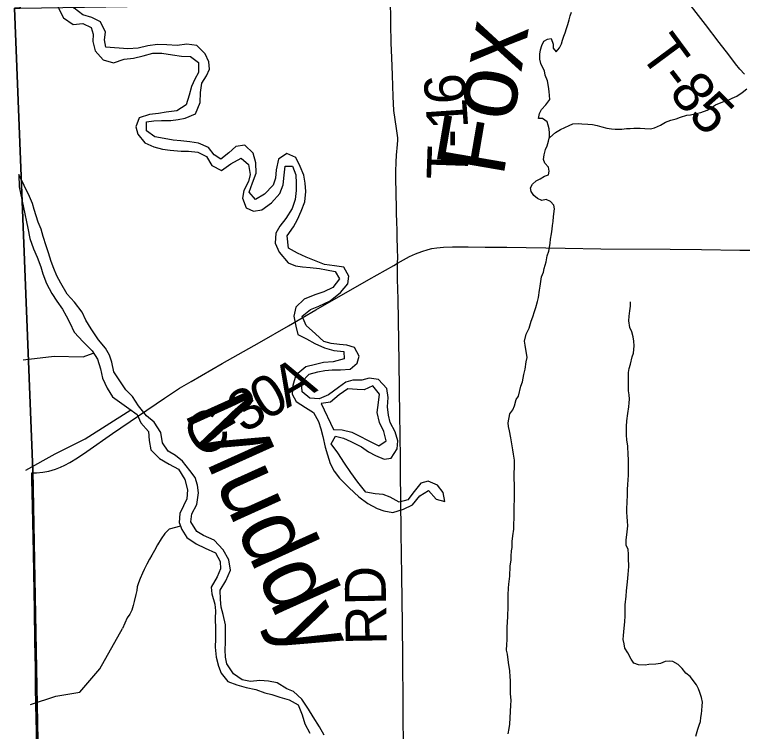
# Model space of a CAD drawing. Extents: x 1985906 to 2360102, y 891258 to 1222054.
# Drawn here: x 2071562 to 2076886, y 1019793 to 1025035 of the extents above; entities that cross this region are included whole.
import ezdxf

# ---------------------------------------------------------------- set-up
doc = ezdxf.new("R2010")
doc.units = 0
for name, color, linetype in [('GM_X_Adjacent_County', 7, 'Continuous'), ('GM_X_County', 7, 'Continuous'), ('GM_X_County_Road', 7, 'Continuous'), ('GM_X_County_Road_Text', 7, 'Continuous'), ('GM_X_Major_River', 7, 'Continuous'), ('GM_X_Major_River_Text', 7, 'Continuous'), ('GM_X_Minor_River', 7, 'Continuous'), ('GM_X_Minor_River_Text', 7, 'Continuous'), ('GM_X_Township', 7, 'Continuous'), ('GM_X_Township_Road', 7, 'Continuous'), ('GM_X_Township_Road_Text', 7, 'Continuous')]:
    doc.layers.add(name, color=color, linetype=linetype)

msp = doc.modelspace()

# ---------------------------------------------------------------- linework, layer by layer
at = {"layer": 'GM_X_Adjacent_County'}
msp.add_lwpolyline([(2071926.7, 1054555.3), (2072166.7, 1051922.6), (2072218.3, 1051577.8), (2072142.8, 1047459), (2072178.7, 1046252), (2072112.2, 1041354.4), (2072120.2, 1038512.6), (2072055.1, 1036106.6), (2072018.3, 1033424.1), (2071939.9, 1030867.8), (2071602.1, 1025081.7), (2071562, 1025081.6), (2071696.9, 1021700.4), (2071829.8, 1014456.9), (2071852.3, 1012905.1), (2071861.2, 1011952), (2071887.5, 1008769)], dxfattribs=at)
at = {"layer": 'GM_X_County'}
msp.add_lwpolyline([(2071887.5, 1008769), (2071861.2, 1011952), (2071852.3, 1012905.1), (2071829.8, 1014456.9), (2071696.9, 1021700.4), (2071562, 1025081.6), (2071602.1, 1025081.7), (2071939.9, 1030867.8), (2072018.3, 1033424.1), (2072055.1, 1036106.6), (2072120.2, 1038512.6), (2072112.2, 1041354.4), (2072178.7, 1046252), (2072142.8, 1047459), (2072218.3, 1051577.8), (2072166.7, 1051922.6), (2071926.7, 1054555.3)], dxfattribs=at)
at = {"layer": 'GM_X_County_Road'}
for points in [[(2074363.8, 1023217), (2074450, 1023264.6), (2074494.1, 1023285.7), (2074539.6, 1023303.3), (2074586.4, 1023317.6), (2074614.9, 1023323.7), (2074650.1, 1023330), (2074698.9, 1023334.4), (2074764.3, 1023336.9), (2074879.1, 1023336.2), (2075003.2, 1023334.4), (2075161.3, 1023332.9), (2075590.2, 1023327.4), (2075850.3, 1023322.8), (2076356.6, 1023318.9), (2076586.2, 1023315.8), (2076867.7, 1023312.7), (2076963, 1023312.3), (2077040.4, 1023312.3)], [(2071687.6, 1021683), (2071723.6, 1021683.7), (2071768.9, 1021688.3), (2071811.9, 1021696), (2071861.7, 1021709.8), (2071898.5, 1021724.4), (2071930, 1021738.9), (2071966.5, 1021758.5), (2072022.6, 1021793.2), (2072090.4, 1021839.7), (2072279.2, 1021970.8), (2072658.4, 1022230.8), (2072768.7, 1022301.9), (2072853, 1022352.6), (2073081.3, 1022482.7), (2073352.3, 1022637.2), (2073566.3, 1022759.3), (2073765.1, 1022874.7), (2074152.2, 1023097.5), (2074335.5, 1023200.7), (2074363.8, 1023217)], [(2071724.7, 1019633.2), (2071721.9, 1019797.2), (2071720.5, 1019879.2), (2071715.4, 1020108.5), (2071714.1, 1020256.1), (2071710.5, 1020452.7), (2071708, 1020682.3), (2071704.8, 1020813.6), (2071700.5, 1021099.1), (2071693.8, 1021436.8), (2071688.6, 1021633.8), (2071687.6, 1021683)]]:
    msp.add_lwpolyline(points, dxfattribs=at)
at = {"layer": 'GM_X_Major_River'}
for points in [[(2071594.5, 1023864.4), (2071596.5, 1023775.9)], [(2072375, 1022290.3), (2072287.9, 1022422.8), (2072273.6, 1022493), (2072255.4, 1022543), (2072227.2, 1022595.1), (2072175, 1022657.1), (2072122.7, 1022737.1), (2072084.5, 1022801.1), (2072056.2, 1022859.2), (2072000, 1022931.2), (2071945.7, 1022991.1), (2071901.4, 1023071.2), (2071871.2, 1023123.2), (2071849, 1023177.2), (2071830.8, 1023229.3), (2071810.6, 1023293.4), (2071794.4, 1023343.5), (2071772.1, 1023411.6), (2071755.9, 1023465.7), (2071733.7, 1023517.7), (2071705.4, 1023610.4), (2071694.1, 1023652.8), (2071671, 1023704), (2071594.5, 1023864.4)], [(2071596.5, 1023775.9), (2071660.2, 1023472.1), (2071674.2, 1023397.2), (2071700.5, 1023321.1), (2071726.7, 1023261), (2071753, 1023188.9), (2071769.2, 1023138.8), (2071795.4, 1023068.8), (2071833.7, 1022994.7), (2071871.9, 1022938.7), (2071912.1, 1022880.7), (2071940.3, 1022830.7), (2071966.5, 1022780.6), (2071996.8, 1022712.6), (2072063.1, 1022642.6), (2072129.3, 1022574.7), (2072169.5, 1022514.7), (2072191.8, 1022444.6), (2072204.1, 1022376.4), (2072238.3, 1022302.4), (2072278.6, 1022240.3), (2072397.8, 1022154.3)], [(2073826.8, 1019765.7), (2073792.4, 1019825.6), (2073746, 1019899.4), (2073711.7, 1019955.3), (2073663.3, 1020029.1), (2073603, 1020084.8), (2073552.9, 1020104.5), (2073482.7, 1020148.2), (2073418.6, 1020159.8), (2073356.6, 1020165.4), (2073288.7, 1020157), (2073226.6, 1020170.7), (2073164.3, 1020214.4), (2073114, 1020286.2), (2073105.7, 1020336.2), (2073101.4, 1020390.2), (2073105.1, 1020442.3), (2073104.7, 1020510.4), (2073104.4, 1020572.5), (2073088, 1020646.5), (2073073.7, 1020700.4), (2073067.4, 1020756.5), (2073067, 1020826.6), (2073106.6, 1020894.9), (2073140.2, 1020971.2), (2073129.8, 1021047.2), (2073087.4, 1021121), (2073021, 1021190.8), (2072944.8, 1021226.3), (2072894.7, 1021254.1), (2072852.3, 1021325.9), (2072857.9, 1021384), (2072895.6, 1021452.3), (2072907.1, 1021538.5), (2072900.8, 1021594.5), (2072882.5, 1021648.5), (2072844.2, 1021700.3), (2072789.9, 1021768.1), (2072739.6, 1021809.8), (2072685.5, 1021841.6), (2072645.1, 1021903.4), (2072632.7, 1021979.4), (2072582.3, 1022053.2), (2072528, 1022101), (2072469.7, 1022174.7), (2072425.3, 1022242.5), (2072375, 1022290.3)], [(2072397.8, 1022154.3), (2072460, 1022110.6), (2072486.3, 1022048.7), (2072542.7, 1021984.9), (2072547, 1021918.9), (2072559.4, 1021850.8), (2072621.8, 1021789.1), (2072692, 1021747.5), (2072760.2, 1021709.8), (2072806.6, 1021636), (2072827, 1021560.1), (2072821.3, 1021493.9), (2072797.6, 1021441.7), (2072772, 1021385.5), (2072766.3, 1021321.4), (2072784.6, 1021269.5), (2072820.9, 1021209.6), (2072891.2, 1021163.9), (2072955.3, 1021132.3), (2073031.5, 1021098.7), (2073065.8, 1021034.8), (2073068.1, 1020982.8), (2073044.5, 1020922.6), (2072998.9, 1020848.2), (2073005.2, 1020798.2), (2073027.6, 1020724.2), (2073031.8, 1020674.2), (2073028.1, 1020618.1), (2073030.6, 1020542), (2073031, 1020469.9), (2073029.3, 1020409.8), (2073037.7, 1020335.8), (2073054.1, 1020269.8), (2073072.3, 1020217.8), (2073120.7, 1020158), (2073188.8, 1020132.4), (2073256.9, 1020114.8), (2073327, 1020099.2), (2073393.1, 1020075.5), (2073443.2, 1020061.8), (2073501.3, 1020044.1), (2073569.4, 1020022.5), (2073635.5, 1019986.8), (2073665.9, 1019914.9), (2073684.3, 1019849), (2073720.7, 1019781.1)]]:
    msp.add_lwpolyline(points, dxfattribs=at)
at = {"layer": 'GM_X_Minor_River'}
for points in [[(2072310.6, 1025418.7), (2072244.6, 1025436.5), (2072194.5, 1025454.3), (2072132.4, 1025492.2), (2072080.3, 1025514.1), (2072008.2, 1025527.9), (2071932.3, 1025509.5), (2071876.5, 1025447.2), (2071848.7, 1025380.9), (2071835, 1025308.7), (2071835.3, 1025244.5), (2071839.4, 1025194.4), (2071865.7, 1025124.3), (2071894, 1025062.3), (2071920.1, 1025010.2), (2071990.3, 1024962.3), (2072062.3, 1024968.6), (2072122.4, 1024940.8), (2072136.6, 1024890.7), (2072134.8, 1024838.5), (2072151.1, 1024770.4), (2072211.3, 1024704.5), (2072285.4, 1024682.7), (2072363.8, 1024709.1)], [(2072391.4, 1024783.3), (2072229, 1024796.8), (2072218.8, 1024848.9), (2072226.6, 1024905), (2072190.3, 1024981.1), (2072128.2, 1025013), (2072062.1, 1025032.8), (2071997.9, 1025080.7), (2071955.6, 1025146.7), (2071947.4, 1025198.8), (2071941.2, 1025254.9), (2071935, 1025325.1), (2071954.8, 1025379.3), (2071986.5, 1025443.6), (2072054.6, 1025435.8), (2072114.7, 1025409.9), (2072164.8, 1025384), (2072236.9, 1025342.2), (2072302.9, 1025338.4)], [(2075183.8, 1022114.2), (2075205.7, 1022144.4), (2075217.5, 1022172.5), (2075231.3, 1022218.8), (2075247.2, 1022244.9), (2075264.9, 1022317.3), (2075276.7, 1022349.4), (2075286.5, 1022403.7), (2075296.3, 1022441.9), (2075304, 1022496.1), (2075311.9, 1022526.2), (2075297.4, 1022616.5), (2075291.2, 1022646.6), (2075303, 1022696.8), (2075326.8, 1022741.1), (2075340.6, 1022793.3), (2075352.4, 1022823.5), (2075364.2, 1022863.7), (2075374.1, 1022891.9), (2075385.9, 1022936.1), (2075393.8, 1022966.2), (2075401.5, 1023020.4), (2075405.3, 1023048.6), (2075417, 1023116.9), (2075430.9, 1023151), (2075436.7, 1023177.2), (2075450.5, 1023225.4), (2075458.3, 1023269.6), (2075470.1, 1023305.8), (2075474, 1023331.9), (2075479.9, 1023362), (2075481.7, 1023392.2), (2075489.5, 1023430.3), (2075493.4, 1023464.5), (2075497.2, 1023492.6), (2075501.1, 1023522.7), (2075502.9, 1023558.8), (2075510.6, 1023615.1), (2075506.5, 1023641.2), (2075482.3, 1023667.1), (2075450.1, 1023683), (2075418.1, 1023674.9), (2075386, 1023690.8), (2075359.8, 1023712.7), (2075339.6, 1023740.7), (2075335.5, 1023768.8), (2075351.4, 1023795), (2075377.3, 1023819.2), (2075405.3, 1023833.4), (2075437.2, 1023853.6), (2075467.2, 1023861.8), (2075471.1, 1023889.9), (2075467, 1023918), (2075440.7, 1023948), (2075430.6, 1023976), (2075434.4, 1024010.2), (2075446.2, 1024048.3), (2075458.1, 1024074.5), (2075468, 1024108.7), (2075473.8, 1024140.8), (2075475.7, 1024166.9), (2075471.5, 1024199), (2075465.3, 1024225.1), (2075457.2, 1024251.1), (2075423, 1024275), (2075395, 1024274.9), (2075400.8, 1024311.1), (2075416.7, 1024341.2), (2075448.5, 1024373.5), (2075476.4, 1024413.8), (2075474.2, 1024441.9), (2075472.1, 1024472), (2075467.9, 1024508.1), (2075459.7, 1024550.2), (2075443.4, 1024592.3), (2075437.2, 1024624.4), (2075423.1, 1024650.4), (2075410.9, 1024676.4), (2075402.7, 1024708.5), (2075404.5, 1024744.7), (2075408.4, 1024776.8), (2075418.2, 1024808.9), (2075434.1, 1024839.1), (2075460.1, 1024855.3), (2075486.1, 1024859.4), (2075500.3, 1024819.4), (2075502.5, 1024789.3), (2075522.7, 1024763.3), (2075546.6, 1024791.5), (2075562.4, 1024821.7), (2075570.3, 1024847.8), (2075578.2, 1024875.9), (2075590.1, 1024902.1), (2075597.9, 1024932.2), (2075607.8, 1024962.4), (2075617.6, 1024996.5), (2075625.5, 1025026.7), (2075635.4, 1025052.8)], [(2073330.3, 1023875.8), (2073325.9, 1023949.8), (2073307.5, 1024021.8), (2073247.1, 1024079.5), (2073181.2, 1024069.1), (2073129.5, 1024022.8), (2073071.7, 1023978.4), (2073021.6, 1024010.1), (2072981.3, 1024061.9), (2072907.1, 1024093.6), (2072845.1, 1024103.2), (2072779, 1024110.8), (2072723, 1024116.5), (2072656.9, 1024128.1), (2072588.9, 1024139.7), (2072526.7, 1024183.4), (2072526.3, 1024251.5), (2072580.2, 1024257.8), (2072636.2, 1024260.2), (2072706.2, 1024260.6), (2072758.2, 1024266.9), (2072810.1, 1024277.2), (2072885.9, 1024309.7), (2072919.5, 1024392), (2072921.1, 1024466.1), (2072930.7, 1024534.2), (2072966.4, 1024586.5), (2072988.1, 1024636.7), (2072983.8, 1024688.7), (2072955.5, 1024746.6), (2072895.2, 1024808.3), (2072823.2, 1024817.9), (2072751.2, 1024807.5), (2072675.2, 1024813), (2072607.2, 1024816.6), (2072537.2, 1024806.2), (2072467.3, 1024789.8), (2072391.4, 1024783.3)], [(2072363.8, 1024709.1), (2072431.8, 1024715.5), (2072503.6, 1024733.9), (2072573.5, 1024752.4), (2072639.5, 1024752.8), (2072717.6, 1024739.2), (2072783.6, 1024731.6), (2072849.6, 1024728), (2072907.9, 1024684.2), (2072908.3, 1024612.2), (2072880.5, 1024561.9), (2072856.8, 1024509.7), (2072839.2, 1024445.6), (2072817.6, 1024375.4), (2072747.8, 1024330.9), (2072671.9, 1024320.4), (2072615.9, 1024312.1), (2072550, 1024303.7), (2072474.1, 1024279.2), (2072448.5, 1024213), (2072464.8, 1024159), (2072515.1, 1024097.2), (2072581.3, 1024067.6), (2072643.4, 1024050), (2072699.4, 1024042.3), (2072779.4, 1024036.7), (2072833.4, 1024035.1), (2072901.5, 1024027.4), (2072965.6, 1023997.8), (2073004, 1023931.9), (2073076.2, 1023894.3), (2073143.9, 1023942.8), (2073219.7, 1023985.3), (2073273.9, 1023937.5), (2073284.3, 1023865.5), (2073272.6, 1023813.4), (2073239, 1023747.1), (2073229.3, 1023691), (2073255.7, 1023621), (2073309.8, 1023597.3), (2073369.7, 1023605.7), (2073441.4, 1023658.2), (2073503.1, 1023726.6), (2073526.7, 1023790.8), (2073534.3, 1023861), (2073542, 1023925.1), (2073593.9, 1023927.4), (2073618.3, 1023863.5), (2073622.6, 1023801.4), (2073622.9, 1023747.3), (2073613.3, 1023683.2), (2073591.6, 1023617), (2073546, 1023544.7), (2073502.4, 1023488.3), (2073472.6, 1023436.1), (2073467, 1023364), (2073497.4, 1023298.1), (2073563.8, 1023220.4), (2073615.9, 1023196.7), (2073668, 1023191), (2073724, 1023185.3), (2073792, 1023177.7), (2073844.1, 1023168), (2073908.1, 1023156.3), (2073938.4, 1023102.4), (2073888.8, 1023038.1), (2073825, 1023007.7), (2073757.1, 1022985.2), (2073681.3, 1022952.8), (2073619.6, 1022894.3), (2073604, 1022828.2), (2073618.3, 1022756.2), (2073632.7, 1022694.2), (2073696.8, 1022664.5), (2073759, 1022628.8), (2073829.2, 1022597.2), (2073897.3, 1022577.6), (2073969.3, 1022570), (2073971.6, 1022517.9), (2073891.7, 1022495.4), (2073821.8, 1022491), (2073763.9, 1022476.7), (2073692, 1022458.2), (2073620.3, 1022397.7), (2073596.7, 1022323.5), (2073593.1, 1022259.4), (2073621.4, 1022205.5), (2073689.6, 1022161.9), (2073747.8, 1022124.2), (2073786.2, 1022058.3), (2073802.4, 1022004.3), (2073816.8, 1021948.3), (2073833.2, 1021870.3), (2073851.5, 1021814.4), (2073869.8, 1021752.4), (2073900.1, 1021696.5), (2073938.4, 1021644.7), (2074008.8, 1021573), (2074081.1, 1021507.4), (2074145.4, 1021459.7), (2074213.6, 1021424)], [(2075473.2, 1024137.6), (2075477.8, 1024136.8), (2075517.7, 1024173.1), (2075555.7, 1024193.4), (2075585.7, 1024209.6), (2075617.6, 1024223.8), (2075645.6, 1024235.9), (2075685.7, 1024238.1), (2075711.8, 1024236.2), (2075753.9, 1024232.4), (2075787.9, 1024230.6), (2075824, 1024224.7), (2075856.2, 1024214.8), (2075894.3, 1024202.9), (2075928.4, 1024199.1), (2075954.4, 1024197.2), (2076004.5, 1024197.4), (2076036.6, 1024201.6), (2076064.6, 1024201.7), (2076090.7, 1024203.8), (2076138.7, 1024204.1), (2076172.8, 1024202.2), (2076212.9, 1024200.4), (2076242.9, 1024206.6), (2076286.9, 1024224.8), (2076322.9, 1024247.1), (2076360.9, 1024263.3), (2076400.9, 1024271.5), (2076432.9, 1024285.7), (2076478.9, 1024298), (2076507, 1024302.1), (2076535, 1024308.3), (2076581, 1024318.5), (2076627, 1024336.8), (2076653, 1024351), (2076688.9, 1024375.2), (2076742.9, 1024397.5), (2076780.9, 1024409.8), (2076810.9, 1024423.9), (2076844.9, 1024438.2), (2076882.8, 1024464.4), (2076916.8, 1024492.7)], [(2074213.6, 1021424), (2074263.7, 1021406.3), (2074327.7, 1021392.7), (2074407.6, 1021417.2), (2074473.4, 1021449.6), (2074527.1, 1021516), (2074588.8, 1021554.4), (2074645.2, 1021490.7), (2074709.3, 1021475), (2074696.9, 1021541), (2074656.6, 1021592.8), (2074586.5, 1021622.5), (2074532.6, 1021608.1), (2074484.9, 1021547.8), (2074437.2, 1021485.4), (2074375.3, 1021469), (2074309.1, 1021504.7), (2074259, 1021526.4), (2074199, 1021530.1), (2074131, 1021541.7), (2074072.6, 1021615.4), (2074022.2, 1021687.2), (2073975.8, 1021755), (2073925.4, 1021830.8), (2073877, 1021896.6), (2073908.7, 1021950.9), (2073966.8, 1021937.2), (2074020.9, 1021913.5), (2074099.1, 1021873.9), (2074151.3, 1021838.2), (2074201.5, 1021810.4), (2074265.6, 1021782.8), (2074317.6, 1021791.1), (2074361.2, 1021859.4), (2074364.9, 1021917.5), (2074346.5, 1021983.5), (2074310.1, 1022051.4), (2074295.8, 1022105.3), (2074289.5, 1022167.4), (2074295.1, 1022235.5), (2074284.8, 1022301.5), (2074224.4, 1022367.2), (2074154.4, 1022376.8), (2074102.5, 1022360.5), (2074036.5, 1022362.1), (2073984.6, 1022345.8), (2073930.8, 1022307.4), (2073859.1, 1022253), (2073789.2, 1022224.5), (2073721.2, 1022230.1), (2073665, 1022275.8), (2073660.6, 1022345.9), (2073716.3, 1022404.3), (2073780.2, 1022422.7), (2073832.1, 1022431), (2073884.1, 1022437.3), (2073946.1, 1022435.7), (2074016, 1022442.1), (2074067.8, 1022484.5), (2074083.5, 1022536.6), (2074047.2, 1022600.5), (2073993.1, 1022616.2), (2073939.1, 1022621.9), (2073877, 1022629.5), (2073824.9, 1022645.2), (2073762.6, 1022700.9), (2073694.3, 1022760.6), (2073665.9, 1022828.5), (2073725.7, 1022878.9), (2073787.5, 1022901.3), (2073871.3, 1022941.9), (2073945, 1023002.4), (2073998.6, 1023066.8), (2074006.3, 1023122.9), (2073970, 1023186.7), (2073901.9, 1023196.3), (2073829.9, 1023207.9), (2073755.7, 1023235.5), (2073695.6, 1023261.2), (2073631.4, 1023290.9), (2073565.2, 1023326.5), (2073556.7, 1023416.6), (2073602.4, 1023482.9), (2073632.1, 1023537.2), (2073657.7, 1023597.4), (2073685.4, 1023665.6), (2073693, 1023741.8), (2073688.6, 1023801.8), (2073678.3, 1023859.8), (2073652, 1023923.7), (2073619.6, 1023989.6), (2073553.4, 1024019.3), (2073491.7, 1023976.9), (2073476.1, 1023898.7), (2073470.4, 1023838.6), (2073452.7, 1023786.4), (2073391.1, 1023722), (2073325.3, 1023683.5), (2073277, 1023735.3), (2073302.7, 1023803.5), (2073330.3, 1023875.8)], [(2076593.5, 1020006.9), (2076587.3, 1020041), (2076575.1, 1020077.1), (2076564.9, 1020105.2), (2076548.7, 1020133.2), (2076502.3, 1020195.2), (2076472.1, 1020219.2), (2076445.9, 1020253.2), (2076415.7, 1020283.1), (2076377.5, 1020305), (2076349.4, 1020306.9), (2076319.4, 1020302.8), (2076285.4, 1020288.5), (2076251.4, 1020284.4), (2076201.3, 1020282.2), (2076173.3, 1020278), (2076125.2, 1020279.8), (2076091, 1020291.7), (2076070.8, 1020321.7), (2076048.6, 1020367.8), (2076026.3, 1020401.8), (2076020.2, 1020433.9), (2076014, 1020464), (2076015.8, 1020494.1), (2076017.7, 1020520.2), (2076025.3, 1020596.5), (2076027.1, 1020634.6), (2076026.8, 1020686.8), (2076028.7, 1020719), (2076034.4, 1020781.2), (2076038.2, 1020821.4), (2076045.8, 1020885.6), (2076049.6, 1020939.9), (2076055.3, 1020998.1), (2076052.9, 1021060.3), (2076052.8, 1021086.4), (2076050.6, 1021124.5), (2076036.4, 1021152.6), (2076036.2, 1021190.7), (2076041.9, 1021251), (2076047.7, 1021295.2), (2076045.5, 1021331.3), (2076043.4, 1021361.4), (2076041.2, 1021395.5), (2076041, 1021423.6), (2076042.8, 1021465.8), (2076044.5, 1021526), (2076044.3, 1021562.1), (2076048.1, 1021598.2), (2076051.8, 1021666.5), (2076051.2, 1021782.9), (2076049, 1021815), (2076046.7, 1021879.3), (2076040.4, 1021925.4), (2076038.2, 1021959.5), (2076038, 1021995.7), (2076037.9, 1022021.7), (2076039.7, 1022063.9), (2076047.4, 1022118.1), (2076055.2, 1022166.3), (2076057, 1022196.5), (2076058.9, 1022222.6), (2076056.7, 1022254.7), (2076052.6, 1022282.8), (2076051.9, 1022417.2), (2076057.7, 1022447.4), (2076067.6, 1022479.5), (2076079.3, 1022531.8), (2076089.2, 1022557.9), (2076092.9, 1022612.1), (2076090.8, 1022646.2), (2076086.6, 1022678.3), (2076076.4, 1022714.4), (2076062.2, 1022746.5), (2076055.9, 1022794.6), (2076057.7, 1022828.8), (2076061.5, 1022868.9), (2076067.4, 1022903.1), (2076067.2, 1022935.2)], [(2071625.9, 1022511), (2071852.4, 1022537.7), (2072063.3, 1022532.6), (2072137.1, 1022558.3)], [(2073894.5, 1022000.9), (2073958.5, 1021997.2), (2074028.6, 1021981.6), (2074078.7, 1021955.9), (2074152.9, 1021918.3), (2074227.1, 1021880.7), (2074278.9, 1021917), (2074262.5, 1021987), (2074232.1, 1022050.9), (2074213.7, 1022124.9), (2074223.3, 1022197), (2074231, 1022259.2), (2074182.7, 1022318.9), (2074118.8, 1022290.5), (2074068.8, 1022294.2), (2073998.8, 1022297.8), (2073935.1, 1022253.4), (2073873.4, 1022201), (2073805.4, 1022190.6)], [(2073805.4, 1022190.6), (2073894.5, 1022000.9)], [(2071644.7, 1021702.1), (2071858.7, 1021821.8), (2072078.3, 1021932.9), (2072413.4, 1022143.3)], [(2075172, 1019775.6), (2075179.8, 1019813.8), (2075183.6, 1019845.9), (2075189.2, 1019938.2), (2075192.9, 1019984.4), (2075194.7, 1020018.6), (2075190.5, 1020070.7), (2075190, 1020165.1), (2075187.8, 1020191.2), (2075185.6, 1020235.3), (2075175.3, 1020295.5), (2075166.9, 1020357.7), (2075160.8, 1020385.8), (2075162.5, 1020427.9), (2075164.4, 1020462.1), (2075163.9, 1020554.4), (2075167.7, 1020592.5), (2075169.5, 1020632.7), (2075173.1, 1020705), (2075172.7, 1020791.3), (2075174.4, 1020839.5), (2075178.3, 1020869.6), (2075184, 1020927.9), (2075187.6, 1021000.1), (2075193.4, 1021046.3), (2075195.2, 1021074.4), (2075197, 1021112.6), (2075200.9, 1021138.7), (2075202.7, 1021180.9), (2075206.5, 1021223), (2075214.2, 1021271.2), (2075214, 1021315.4), (2075215.9, 1021345.5), (2075215.3, 1021449.9), (2075219.2, 1021480), (2075218.5, 1021604.5), (2075216.4, 1021632.6), (2075216.2, 1021660.7), (2075217.8, 1021743), (2075217.6, 1021775.1), (2075211.4, 1021819.2), (2075207.2, 1021851.3), (2075196.9, 1021909.5), (2075190.7, 1021939.6), (2075182.4, 1021989.7), (2075174.2, 1022021.8), (2075172.1, 1022049.9), (2075183.8, 1022114.2)], [(2072776.1, 1021293.6), (2072693.4, 1021271.7), (2072661.5, 1021239.4), (2072633.7, 1021201.2), (2072607.8, 1021156.9), (2072586, 1021114.6), (2072566.1, 1021082.4), (2072548.3, 1021052.2), (2072530.4, 1021016), (2072510.6, 1020977.8), (2072496.7, 1020949.6), (2072480.9, 1020911.4), (2072469, 1020879.2), (2072459.2, 1020849.1), (2072457.3, 1020823), (2072449.4, 1020792.8), (2072437.7, 1020742.6), (2072429.8, 1020714.4), (2072420, 1020678.3), (2072406.1, 1020650.1), (2072386.2, 1020623.9), (2072352.2, 1020545.8)], [(2071677.6, 1019990.2), (2071863.8, 1020049.5), (2072038.5, 1020080.1), (2072186.1, 1020249.8), (2072352.2, 1020545.8)], [(2076544.7, 1019757.8), (2076560.5, 1019810), (2076568.3, 1019838.2), (2076578.2, 1019866.3), (2076582.1, 1019894.5), (2076585.9, 1019920.6), (2076589.8, 1019946.7), (2076591.6, 1019978.8), (2076593.5, 1020006.9)]]:
    msp.add_lwpolyline(points, dxfattribs=at)
at = {"layer": 'GM_X_Township'}
msp.add_lwpolyline([(2071887.5, 1008769), (2071861.2, 1011952), (2071852.3, 1012905.1), (2071829.8, 1014456.9), (2071696.9, 1021700.4), (2071562, 1025081.6), (2071602.1, 1025081.7), (2074264, 1025122.4), (2076405.9, 1025155.2), (2079654.5, 1025204.9), (2081728.4, 1025236.6), (2086577.8, 1025306.1), (2087095.5, 1025303.4), (2089225.7, 1025330.9), (2092097.4, 1025367.8), (2095094.6, 1025388.3)], dxfattribs=at)
at = {"layer": 'GM_X_Township_Road'}
for points in [[(2076900.1, 1024599.4), (2076866.7, 1024635.9), (2076835.1, 1024673.8), (2076785.3, 1024739.3), (2076716.6, 1024831.3), (2076616.3, 1024961), (2076436.7, 1025194.6)], [(2074363.8, 1023217), (2074364.9, 1023257.6), (2074364.9, 1023278), (2074363.8, 1023297.8), (2074362, 1023330.8), (2074361.7, 1023347.7), (2074361.3, 1023380.5), (2074360.1, 1023422.3), (2074359.2, 1023466.2), (2074358.3, 1023508.4), (2074356.5, 1023591), (2074352.6, 1023757.2), (2074351.2, 1023810), (2074351.6, 1023839.4), (2074350.3, 1023888.3), (2074352.1, 1023955.3), (2074356.6, 1024005.6), (2074362.6, 1024083.9), (2074364.7, 1024116.9), (2074365, 1024133.8), (2074363.8, 1024150.4), (2074355.7, 1024202.1), (2074345, 1024267.6), (2074336, 1024333.2), (2074330.6, 1024436.4), (2074325.3, 1024590.7), (2074320.7, 1024721.7), (2074317.2, 1024826.8), (2074313.7, 1024967.6), (2074310.7, 1025168.4)], [(2074406.2, 1019610), (2074404.4, 1019985.1), (2074401.8, 1020329.7), (2074399.2, 1020577.4), (2074394.4, 1020934.1), (2074389.8, 1021245.9), (2074387.3, 1021492.1), (2074385.9, 1021673.2), (2074384.1, 1021779.1), (2074381.2, 1021968.2), (2074379.1, 1022099.5), (2074374.5, 1022493.5), (2074366.9, 1022953.1), (2074363.3, 1023100.7), (2074362.1, 1023182.8), (2074363.8, 1023217)]]:
    msp.add_lwpolyline(points, dxfattribs=at)

# ---------------------------------------------------------------- texts
at = {"layer": 'GM_X_County_Road_Text'}
for s, rotation, p in [('A', 29.9563, (2073555.4, 1022153.8)), ('0', 29.9869, (2073395.4, 1022061.4)), ('3', 30.0873, (2073235.6, 1021968.9)), ('C', 31.3182, (2072920.2, 1021779.5)), ('-', 30.3205, (2073129.5, 1021906.8))]:
    msp.add_text(s, height=300, rotation=rotation, dxfattribs=at).set_placement(p)
at = {"layer": 'GM_X_Major_River_Text'}
msp.add_text('Muddy', height=500.1, rotation=294.263, dxfattribs=at).set_placement((2072798.5, 1022128.8))
at = {"layer": 'GM_X_Minor_River_Text'}
msp.add_text('Fox', height=500.08, rotation=80.2591, dxfattribs=at).set_placement((2075135.5, 1023838.8))
at = {"layer": 'GM_X_Township_Road_Text'}
for s, rotation, p in [('T', 306.5172, (2076126.9, 1024749.2)), ('-', 307.5997, (2076264.1, 1024563.9)), ('8', 308.0474, (2076340.9, 1024464.3)), ('6', 94.0598, (2074867.8, 1024390.5)), ('5', 314.8206, (2076480.3, 1024289.8)), ('1', 93.9572, (2074880.6, 1024205.5)), ('-', 90.5541, (2074882.6, 1024062.9)), ('T', 87.9982, (2074874.6, 1023824.1)), ('RD', 90.9882, (2074284.6, 1020426.5))]:
    msp.add_text(s, height=300, rotation=rotation, dxfattribs=at).set_placement(p)

doc.saveas('drawing.dxf')
